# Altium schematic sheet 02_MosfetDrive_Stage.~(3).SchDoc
size A4; SheetNumber: 2; SheetTotal: 2
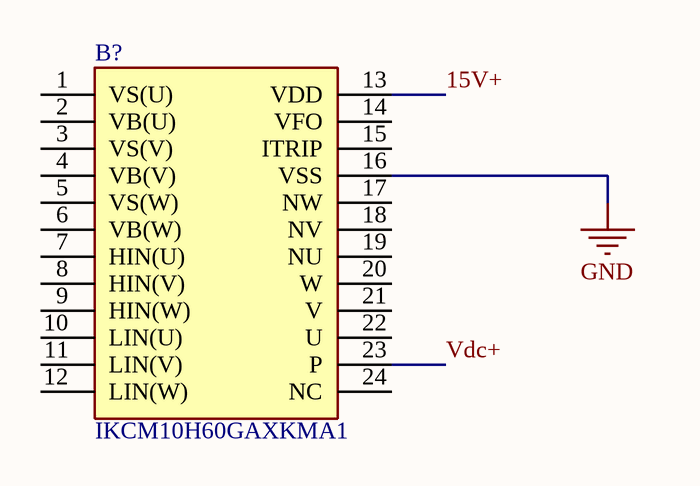
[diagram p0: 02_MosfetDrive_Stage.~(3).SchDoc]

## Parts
B?  IKCM10H60GAXKMA1  [997_IKCM10H60GAXKMA1]

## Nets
GND: B?.16(VSS)
15V+: B?.13(VDD)
Vdc+: B?.23(P)

Not connected (* = marked no-connect by the designer): B? 1(VS(U)) 2(VB(U)) 3(VS(V)) 4(VB(V)) 5(VS(W)) 6(VB(W)) 7(HIN(U)) 8(HIN(V)) 9(HIN(W)) 10(LIN(U)) 11(LIN(V)) 12(LIN(W)) 14(VFO) 15(ITRIP) 17(NW) 18(NV) 19(NU) 20(W) 21(V) 22(U) 24(NC)

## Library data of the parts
B? = IKCM10H60GAXKMA1: Intelligent Power Module 3-Ph 600V 10A; Manufacturer_Name: Infineon; Geometry.Height: 5.6mm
